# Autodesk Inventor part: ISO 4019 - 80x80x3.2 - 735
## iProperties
Created: 2007-05
Part Number: ISO 4019 - 80x80x3.2 - 735
Material: Steel, Mild
Description: Cold-Finished Hollow Section
Vendor: Autodesk Inc.
Document SubType Name: Modeling
Standard: ISO 4019
Designer: kurs1
Standards Organization: ISO
Language: en-US
Size Designation: 80x80x3.2 - 735
Categories: <MemberInstance Version="R10.0.0"><Categories><Category DisplayName="Steel Shapes" InternalName="089c4875-fa83-4c05-b084-43b9cc11f5ed" Mnemonic="GRDR"><Category
Stock Number: 80x80x3.2
Density: 1 g/cm^3
G_L: 735,000 mm
Author: kurs1
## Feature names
1. Body [Extrusion]
2. Fillet1
3. Fillet2
